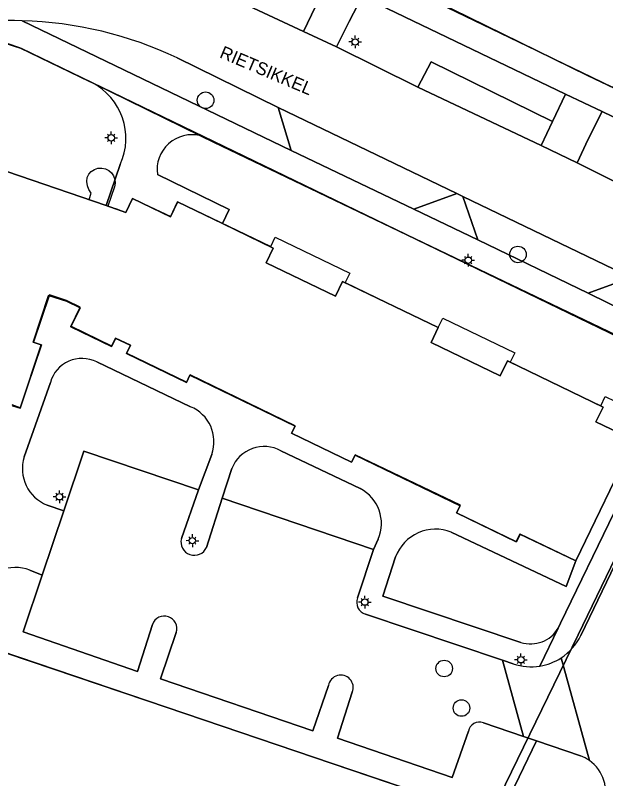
# Model space of a CAD drawing. Extents: x 124901 to 125496, y 515369 to 515789.
# Drawn here: x 125419.8 to 125466.2, y 515550.2 to 515610.2 of the extents above; entities that cross this region are included whole.
import ezdxf

# ---------------------------------------------------------------- set-up
doc = ezdxf.new("R2010")
doc.units = 0
for name, color, linetype in [('Gebouw', 7, 'Continuous'), ('Inrit', 7, 'Continuous'), ('Lichtmast', 7, 'Continuous'), ('Onbegroeid terrein', 7, 'Continuous'), ('Parkeren', 7, 'Continuous'), ('Perceelsgrenzen', 7, 'Continuous'), ('Putten', 7, 'Continuous'), ('Teksten', 7, 'Continuous'), ('Vegetatie', 7, 'Continuous'), ('Voetpad', 7, 'Continuous'), ('Wegen lokale weg', 7, 'Continuous')]:
    doc.layers.add(name, color=color, linetype=linetype)

msp = doc.modelspace()

# ---------------------------------------------------------------- linework, layer by layer
at = {"layer": 'Gebouw'}
for points in [[(125419.556, 515579.495), (125420.172, 515579.297), (125421.812, 515584.271), (125421.185, 515584.478), (125422.401, 515588.171), (125423.795, 515587.712), (125424.876, 515587.192), (125424.156, 515585.696), (125427.353, 515584.158), (125427.669, 515584.816), (125428.841, 515584.253), (125428.525, 515583.595), (125433.24, 515581.318), (125433.514, 515581.885), (125441.779, 515577.891), (125441.505, 515577.324), (125446.214, 515575.048), (125446.488, 515575.615), (125454.753, 515571.621), (125454.479, 515571.054), (125459.171, 515568.787), (125459.447, 515569.38), (125463.856, 515567.282), (125468.431, 515576.794), (125465.425, 515578.219), (125465.99, 515579.39), (125458.478, 515583.015), (125457.913, 515581.844), (125452.472, 515584.475), (125453.036, 515585.646), (125445.513, 515589.27), (125444.949, 515588.099), (125439.495, 515590.726), (125440.059, 515591.897), (125436.074, 515593.82), (125432.537, 515595.527), (125431.973, 515594.356), (125429.004, 515595.783), (125428.479, 515594.7), (125426.916, 515595.234), (125417.181, 515598.559)], [(125451.959, 515548.886), (125415.703, 515561.183)]]:
    msp.add_lwpolyline(points, dxfattribs=at)
at = {"layer": 'Inrit'}
for points in [[(125447.051, 515611.707), (125444.402, 515613.086), (125443.375, 515610.9), (125442.448, 515608.927), (125445.037, 515607.711), (125446.027, 515609.707)], [(125463.951, 515598.605), (125464.82, 515600.459), (125465.919, 515602.634), (125463.045, 515604.005), (125462.026, 515601.858), (125461.12, 515599.948)]]:
    msp.add_lwpolyline(points, close=True, dxfattribs=at)
for points in [[(125458.929, 515559.193), (125458.086, 515559.475), (125459.724, 515553.478), (125460.746, 515553.133), (125464.227, 515551.96)], [(125464.919, 515551.588), (125462.697, 515559.658)]]:
    msp.add_lwpolyline(points, dxfattribs=at)
for centre, radius, start, end in [((125460.335, 515563.279), 4.323, 279.16973, 303.11628), ((125460.34, 515563.284), 4.327, 250.97231, 279.09765), ((125463.121, 515549.073), 3.091, 54.43853, 69.03899)]:
    msp.add_arc(centre, radius, start, end, dxfattribs=at)
at = {"layer": 'Lichtmast'}
for p, q in [((125446.293, 515608.319), (125446.223, 515608.39)), ((125446.505, 515608.407), (125446.505, 515608.607)), ((125446.717, 515608.319), (125446.788, 515608.391)), ((125446.205, 515608.108), (125446.005, 515608.107)), ((125446.293, 515607.895), (125446.221, 515607.824)), ((125446.505, 515607.807), (125446.505, 515607.607)), ((125446.717, 515607.895), (125446.787, 515607.824)), ((125446.805, 515608.107), (125447.005, 515608.107)), ((125427.32, 515600.864), (125427.32, 515601.064)), ((125427.02, 515600.565), (125426.82, 515600.564)), ((125427.108, 515600.352), (125427.036, 515600.281)), ((125427.108, 515600.776), (125427.038, 515600.847)), ((125427.532, 515600.776), (125427.603, 515600.848)), ((125427.532, 515600.352), (125427.602, 515600.281)), ((125427.62, 515600.564), (125427.82, 515600.564)), ((125427.32, 515600.264), (125427.32, 515600.064)), ((125455.393, 515591.236), (125455.393, 515591.436)), ((125455.093, 515590.937), (125454.893, 515590.936)), ((125455.181, 515590.724), (125455.109, 515590.653)), ((125455.181, 515591.148), (125455.111, 515591.219)), ((125455.605, 515591.148), (125455.676, 515591.22)), ((125455.605, 515590.724), (125455.675, 515590.653)), ((125455.693, 515590.936), (125455.893, 515590.936)), ((125455.393, 515590.636), (125455.393, 515590.436)), ((125423.248, 515572.627), (125423.248, 515572.827)), ((125422.948, 515572.328), (125422.748, 515572.327)), ((125423.036, 515572.115), (125422.964, 515572.044)), ((125423.036, 515572.539), (125422.966, 515572.61)), ((125423.46, 515572.539), (125423.531, 515572.611)), ((125423.46, 515572.115), (125423.53, 515572.044)), ((125423.548, 515572.327), (125423.748, 515572.327)), ((125423.248, 515572.027), (125423.248, 515571.827)), ((125433.488, 515569.088), (125433.418, 515569.159)), ((125433.7, 515569.176), (125433.7, 515569.376)), ((125433.912, 515569.088), (125433.983, 515569.16)), ((125433.4, 515568.877), (125433.2, 515568.876)), ((125433.488, 515568.664), (125433.416, 515568.593)), ((125433.7, 515568.576), (125433.7, 515568.376)), ((125433.912, 515568.664), (125433.982, 515568.593)), ((125434, 515568.876), (125434.2, 515568.876)), ((125447.046, 515564.256), (125446.976, 515564.327)), ((125447.258, 515564.344), (125447.258, 515564.544)), ((125447.47, 515564.256), (125447.541, 515564.328)), ((125446.958, 515564.045), (125446.758, 515564.044)), ((125447.046, 515563.832), (125446.974, 515563.761)), ((125447.258, 515563.744), (125447.258, 515563.544)), ((125447.47, 515563.832), (125447.54, 515563.761)), ((125447.558, 515564.044), (125447.758, 515564.044)), ((125459.234, 515559.509), (125459.034, 515559.508)), ((125459.322, 515559.72), (125459.252, 515559.791)), ((125459.534, 515559.808), (125459.534, 515560.008)), ((125459.746, 515559.72), (125459.817, 515559.792)), ((125459.834, 515559.508), (125460.034, 515559.508)), ((125459.322, 515559.296), (125459.25, 515559.225)), ((125459.534, 515559.208), (125459.534, 515559.008)), ((125459.746, 515559.296), (125459.816, 515559.225))]:
    msp.add_line(p, q, dxfattribs=at)
for centre in [(125446.505, 515608.107), (125427.32, 515600.564), (125455.393, 515590.936), (125423.248, 515572.327), (125433.7, 515568.876), (125447.258, 515564.044), (125459.534, 515559.508)]:
    msp.add_circle(centre, 0.25, dxfattribs=at)
at = {"layer": 'Onbegroeid terrein'}
for points in [[(125451.494, 515611.999), (125464.767, 515605.477), (125476.787, 515599.744), (125484.149, 515596.172), (125487.957, 515594.324), (125490.925, 515592.879)], [(125425.786, 515604.912), (125425.621, 515604.992), (125420.143, 515607.655), (125419.23, 515607.963)], [(125434.345, 515600.727), (125425.786, 515604.912)], [(125469.653, 515583.776), (125469.598, 515583.803), (125435.364, 515600.229), (125434.345, 515600.727)], [(125417.181, 515598.559), (125426.916, 515595.234), (125428.033, 515598.474)], [(125428.033, 515598.474), (125426.916, 515595.234), (125428.479, 515594.7), (125429.004, 515595.783), (125431.973, 515594.356), (125432.537, 515595.527), (125436.074, 515593.82)], [(125436.074, 515593.82), (125436.604, 515594.918), (125430.956, 515597.675)], [(125430.956, 515597.675), (125436.604, 515594.918), (125436.074, 515593.82), (125440.059, 515591.897), (125439.495, 515590.726), (125444.949, 515588.099), (125445.513, 515589.27), (125453.036, 515585.646), (125452.472, 515584.475), (125457.913, 515581.844)], [(125454.054, 515569.543), (125463.096, 515565.263), (125463.856, 515567.282), (125459.447, 515569.38), (125459.171, 515568.787), (125454.479, 515571.054), (125454.753, 515571.621), (125446.488, 515575.615), (125446.214, 515575.048), (125441.505, 515577.324), (125441.779, 515577.891), (125433.514, 515581.885), (125433.24, 515581.318), (125428.525, 515583.595), (125428.841, 515584.253), (125427.669, 515584.816), (125427.353, 515584.158), (125424.156, 515585.696), (125424.876, 515587.192), (125423.795, 515587.712), (125422.401, 515588.171), (125421.185, 515584.478), (125421.812, 515584.271), (125420.172, 515579.297), (125419.556, 515579.495)], [(125433.55, 515579.411), (125426.178, 515582.941)], [(125426.178, 515582.941), (125433.55, 515579.411)], [(125457.913, 515581.844), (125458.478, 515583.015), (125465.99, 515579.39), (125465.425, 515578.219), (125468.431, 515576.794), (125463.856, 515567.282), (125463.096, 515565.263), (125454.054, 515569.543)], [(125422.534, 515581.322), (125420.477, 515575.459)], [(125420.477, 515575.459), (125422.534, 515581.322)], [(125462.463, 515561.987), (125462.655, 515562.385), (125471.076, 515579.802)], [(125432.839, 515569.042), (125434.188, 515572.879), (125425.165, 515575.917), (125423.593, 515571.236), (125421.889, 515566.163), (125420.396, 515561.717), (125429.399, 515558.594), (125430.564, 515562.286)], [(125422.28, 515571.677), (125423.593, 515571.236), (125425.165, 515575.917), (125434.188, 515572.879), (125435.229, 515575.667)], [(125446.889, 515572.974), (125440.66, 515575.953)], [(125440.66, 515575.953), (125446.889, 515572.974)], [(125435.229, 515575.667), (125434.188, 515572.879), (125432.839, 515569.042)], [(125434.816, 515568.35), (125436.048, 515572.207), (125436.798, 515574.559)], [(125436.798, 515574.559), (125436.048, 515572.207), (125447.946, 515568.174)], [(125446.677, 515564.371), (125447.946, 515568.174), (125436.048, 515572.207), (125434.816, 515568.35)], [(125420.924, 515566.554), (125421.889, 515566.163), (125423.593, 515571.236), (125422.28, 515571.677)], [(125448.305, 515568.992), (125447.946, 515568.174), (125446.677, 515564.371)], [(125447.946, 515568.174), (125448.305, 515568.992)], [(125459.538, 515560.878), (125448.687, 515564.508), (125449.685, 515567.595)], [(125449.685, 515567.595), (125448.687, 515564.508), (125459.538, 515560.878)], [(125430.564, 515562.286), (125429.399, 515558.594), (125420.396, 515561.717), (125421.889, 515566.163), (125420.924, 515566.554)], [(125416.968, 515564.771), (125415.703, 515561.183), (125451.959, 515548.886), (125449.741, 515542.307), (125451.927, 515541.579), (125450.672, 515537.819), (125444.793, 515539.793)], [(125447.306, 515563.086), (125458.086, 515559.475), (125458.929, 515559.193)], [(125456.581, 515554.537), (125459.724, 515553.478), (125458.086, 515559.475), (125447.306, 515563.086)], [(125461.024, 515559.011), (125462.463, 515561.987)], [(125444.409, 515557.496), (125443.163, 515553.92), (125431.19, 515557.997), (125432.432, 515561.653)], [(125432.432, 515561.653), (125431.19, 515557.997), (125443.163, 515553.92), (125444.409, 515557.496)], [(125455.404, 515553.88), (125454.128, 515550.241), (125445.122, 515553.336), (125446.276, 515556.963)], [(125446.276, 515556.963), (125445.122, 515553.336), (125454.128, 515550.241), (125455.404, 515553.88)], [(125452.256, 515535.48), (125460.746, 515553.133), (125459.724, 515553.478), (125456.581, 515554.537)]]:
    msp.add_lwpolyline(points, dxfattribs=at)
for centre, radius, start, end in [((125423.533, 515600.515), 4.941, 335.60818, 62.87198), ((125423.533, 515600.515), 4.941, 335.60818, 62.87198), ((125433.674, 515598.064), 2.746, 75.85891, 188.151), ((125433.674, 515598.064), 2.746, 75.85891, 188.151), ((125425.024, 515580.627), 2.586, 63.50503, 164.40535), ((125425.024, 515580.627), 2.586, 63.50503, 164.40535), ((125432.434, 515576.662), 2.967, 340.40888, 67.8989), ((125432.434, 515576.662), 2.967, 340.40888, 67.8989), ((125439.352, 515573.53), 2.753, 61.63406, 158.06033), ((125439.352, 515573.53), 2.753, 61.63406, 158.06033), ((125423.412, 515574.538), 3.076, 162.57046, 248.40679), ((125423.412, 515574.538), 3.076, 162.57046, 248.40679), ((125445.48, 515570.23), 3.085, 336.33343, 62.81736), ((125445.48, 515570.23), 3.085, 336.33343, 62.81736), ((125452.81, 515566.459), 3.325, 68.03941, 160.02178), ((125452.81, 515566.459), 3.325, 68.03941, 160.02178), ((125433.855, 515568.774), 1.051, 165.2019, 336.21542), ((125433.855, 515568.774), 1.051, 165.2019, 336.21542), ((125419.797, 515563.775), 2.999, 67.91499, 160.60793), ((125419.797, 515563.775), 2.999, 67.91499, 160.60793), ((125447.619, 515564.036), 1, 160.41266, 251.75029), ((125447.619, 515564.036), 1, 160.41266, 251.75029), ((125431.495, 515561.961), 0.986, 341.79692, 160.76363), ((125431.495, 515561.961), 0.986, 341.79692, 160.76363), ((125460.3, 515563.279), 2.519, 252.38012, 329.14786), ((125460.3, 515563.279), 2.519, 252.38012, 329.14786), ((125460.34, 515563.284), 4.327, 250.97231, 279.09765), ((125445.37, 515557.327), 0.976, 338.08675, 170.04678), ((125445.37, 515557.327), 0.976, 338.08675, 170.04678), ((125456.262, 515553.726), 0.872, 68.51689, 169.82352), ((125456.262, 515553.726), 0.872, 68.51689, 169.82352)]:
    msp.add_arc(centre, radius, start, end, dxfattribs=at)
at = {"layer": 'Parkeren'}
for points in [[(125442.448, 515608.927), (125443.375, 515610.9), (125437.399, 515613.708), (125436.536, 515611.705)], [(125462.026, 515601.858), (125452.479, 515606.551), (125451.427, 515604.548), (125461.12, 515599.948)], [(125441.468, 515599.574), (125451.12, 515594.943), (125454.499, 515596.185), (125440.455, 515602.948)], [(125456.152, 515592.529), (125464.824, 515588.351), (125468.213, 515589.583), (125454.973, 515595.957)]]:
    msp.add_lwpolyline(points, close=True, dxfattribs=at)
at = {"layer": 'Perceelsgrenzen'}
msp.add_lwpolyline([(125466.757, 515604.514), (125464.319, 515605.693), (125448.8, 515613.204), (125453.982, 515624.032), (125454.428, 515623.816), (125454.483, 515623.931), (125455.417, 515625.125), (125456.7, 515627.855), (125457.727, 515629.976), (125458.438, 515631.48), (125458.516, 515632.25), (125458.523, 515632.331), (125462.144, 515639.859), (125462.19, 515639.955), (125479.405, 515631.655), (125479.182, 515631.185), (125475.333, 515623.083), (125475.644, 515622.957), (125470.796, 515612.896)], close=True, dxfattribs=at)
for points in [[(125490.925, 515592.833), (125488.337, 515594.082), (125483.848, 515596.248), (125466.757, 515604.514), (125464.319, 515605.693), (125448.8, 515613.204)], [(125445.448, 515523.259), (125464.025, 515561.476), (125473.175, 515580.417), (125473.449, 515581.117), (125473.602, 515581.789), (125420.253, 515607.597), (125418.809, 515608.056)], [(125418.809, 515608.056), (125420.253, 515607.597), (125473.602, 515581.789), (125473.449, 515581.117), (125473.175, 515580.417), (125464.025, 515561.476), (125445.448, 515523.259)], [(125417.192, 515598.56), (125425.578, 515595.707), (125425.74, 515596.222), (125425.563, 515596.494), (125425.448, 515596.796), (125425.399, 515597.117), (125425.419, 515597.44), (125425.554, 515597.7), (125425.752, 515597.917), (125425.998, 515598.076), (125426.276, 515598.168), (125426.569, 515598.185), (125426.857, 515598.127), (125427.12, 515597.998), (125427.341, 515597.806), (125427.506, 515597.563), (125427.604, 515597.287), (125427.628, 515596.995), (125427.577, 515596.706), (125427.065, 515595.201), (125427.814, 515594.946), (125428.479, 515594.7), (125429.004, 515595.783), (125429.495, 515595.563), (125431.996, 515594.367), (125432.552, 515595.534), (125439.863, 515592.006), (125440.219, 515592.743), (125446.071, 515589.919), (125445.715, 515589.181), (125453.035, 515585.648), (125453.392, 515586.386), (125459.052, 515583.653), (125458.695, 515582.915), (125465.807, 515579.483), (125466.168, 515580.228), (125470.705, 515578.023)], [(125417.192, 515598.56), (125425.578, 515595.707), (125425.74, 515596.222), (125425.563, 515596.494), (125425.448, 515596.796), (125425.399, 515597.117), (125425.419, 515597.44), (125425.554, 515597.7), (125425.752, 515597.917), (125425.998, 515598.076), (125426.276, 515598.168), (125426.569, 515598.185), (125426.857, 515598.127), (125427.12, 515597.998), (125427.341, 515597.806), (125427.506, 515597.563), (125427.604, 515597.287), (125427.628, 515596.995), (125427.577, 515596.706), (125427.065, 515595.201), (125427.814, 515594.946), (125428.479, 515594.7), (125429.004, 515595.783), (125429.495, 515595.563), (125431.996, 515594.367), (125432.552, 515595.534), (125439.863, 515592.006), (125440.219, 515592.743), (125446.071, 515589.919), (125445.715, 515589.181), (125453.035, 515585.648), (125453.392, 515586.386), (125459.052, 515583.653), (125458.695, 515582.915), (125465.807, 515579.483), (125466.168, 515580.228), (125470.705, 515578.023)], [(125467.779, 515575.432), (125463.848, 515567.282), (125459.464, 515569.389), (125459.174, 515568.786), (125454.48, 515571.079), (125454.775, 515571.665), (125446.499, 515575.626), (125446.218, 515575.041), (125441.506, 515577.32), (125441.794, 515577.915), (125433.524, 515581.916), (125433.245, 515581.339), (125428.534, 515583.618), (125428.826, 515584.222), (125427.654, 515584.789), (125427.362, 515584.185), (125424.155, 515585.737), (125424.52, 515586.491), (125424.883, 515587.241), (125423.802, 515587.764), (125422.476, 515588.214), (125421.215, 515584.499), (125421.851, 515584.284), (125420.171, 515579.334), (125419.536, 515579.55)], [(125467.779, 515575.432), (125463.848, 515567.282), (125459.464, 515569.389), (125459.174, 515568.786), (125454.48, 515571.079), (125454.775, 515571.665), (125446.499, 515575.626), (125446.218, 515575.041), (125441.506, 515577.32), (125441.794, 515577.915), (125433.524, 515581.916), (125433.245, 515581.339), (125428.534, 515583.618), (125428.826, 515584.222), (125427.654, 515584.789), (125427.362, 515584.185), (125424.155, 515585.737), (125424.52, 515586.491), (125424.883, 515587.241), (125423.802, 515587.764), (125422.476, 515588.214), (125421.215, 515584.499), (125421.851, 515584.284), (125420.171, 515579.334), (125419.536, 515579.55)], [(125413.545, 515561.895), (125451.956, 515548.9)], [(125413.545, 515561.895), (125451.956, 515548.9)]]:
    msp.add_lwpolyline(points, dxfattribs=at)
at = {"layer": 'Putten'}
for centre in [(125434.74, 515603.52), (125459.3, 515591.39), (125453.5, 515558.82), (125454.86, 515555.71)]:
    msp.add_circle(centre, 0.65, dxfattribs=at)
at = {"layer": 'Vegetatie'}
for points in [[(125462.026, 515601.858), (125463.045, 515604.005), (125447.051, 515611.707), (125446.027, 515609.707), (125445.037, 515607.711), (125451.427, 515604.548), (125452.479, 515606.551)], [(125481.066, 515595.303), (125465.919, 515602.634), (125464.82, 515600.459), (125463.951, 515598.605), (125472.094, 515594.536), (125474.999, 515595.659), (125475.486, 515595.426), (125480.04, 515593.186)], [(125456.152, 515592.529), (125454.973, 515595.957), (125454.499, 515596.185), (125451.12, 515594.943)]]:
    msp.add_lwpolyline(points, close=True, dxfattribs=at)
for points in [[(125420.322, 515609.779), (125441.468, 515599.574)], [(125441.468, 515599.574), (125440.455, 515602.948), (125432.512, 515606.845)], [(125468.213, 515589.583), (125464.824, 515588.351), (125473.838, 515583.91)]]:
    msp.add_lwpolyline(points, dxfattribs=at)
msp.add_arc((125419.464, 515579.424), 30.367, 64.55301, 88.38087, dxfattribs=at)
at = {"layer": 'Voetpad'}
for points in [[(125447.051, 515611.707), (125463.045, 515604.005), (125465.919, 515602.634), (125481.066, 515595.303), (125483.202, 515594.293), (125484.149, 515596.172), (125476.787, 515599.744), (125464.767, 515605.477), (125451.494, 515611.999)], [(125451.12, 515594.943), (125441.468, 515599.574), (125420.322, 515609.779)], [(125419.23, 515607.963), (125420.143, 515607.655), (125425.621, 515604.992), (125425.786, 515604.912), (125434.345, 515600.727), (125435.364, 515600.229), (125469.598, 515583.803), (125469.653, 515583.776), (125473.811, 515581.782)], [(125473.838, 515583.91), (125464.824, 515588.351), (125456.152, 515592.529), (125451.12, 515594.943)], [(125464.242, 515561.43), (125473.342, 515580.329)], [(125471.076, 515579.802), (125462.655, 515562.385), (125462.463, 515561.987), (125461.024, 515559.011)], [(125460.746, 515553.133), (125452.256, 515535.48)], [(125464.227, 515551.96), (125460.746, 515553.133)]]:
    msp.add_lwpolyline(points, dxfattribs=at)
for centre, radius, start, end in [((125419.463, 515579.455), 30.336, 88.37675, 106.37937), ((125460.329, 515563.282), 4.329, 303.15901, 334.67089), ((125460.335, 515563.279), 4.323, 279.16973, 303.11628), ((125463.121, 515549.073), 3.091, 54.43853, 69.03899), ((125463.141, 515549.108), 3.051, 339.95739, 54.36906)]:
    msp.add_arc(centre, radius, start, end, dxfattribs=at)
at = {"layer": 'Wegen lokale weg'}
for points in [[(125432.512, 515606.845), (125440.455, 515602.948), (125454.499, 515596.185), (125454.973, 515595.957), (125468.213, 515589.583), (125470.574, 515588.39), (125478.274, 515584.511), (125481.106, 515590.131), (125479.044, 515591.131), (125474.467, 515593.35), (125472.094, 515594.536), (125463.951, 515598.605), (125461.12, 515599.948), (125451.427, 515604.548), (125445.037, 515607.711), (125442.448, 515608.927), (125436.536, 515611.705)], [(125473.342, 515580.329), (125464.242, 515561.43)], [(125462.697, 515559.658), (125464.919, 515551.588)]]:
    msp.add_lwpolyline(points, dxfattribs=at)
for centre, radius, start, end in [((125419.463, 515579.455), 30.336, 88.37675, 106.37937), ((125419.464, 515579.424), 30.367, 64.55301, 88.38087), ((125460.329, 515563.282), 4.329, 303.15901, 334.67089), ((125463.141, 515549.108), 3.051, 339.95739, 54.36906)]:
    msp.add_arc(centre, radius, start, end, dxfattribs=at)

# ---------------------------------------------------------------- texts
at = {"layer": 'Teksten'}
msp.add_text('RIETSIKKEL', height=1, rotation=337, dxfattribs=at).set_placement((125435.772, 515606.91))

doc.saveas('drawing.dxf')
